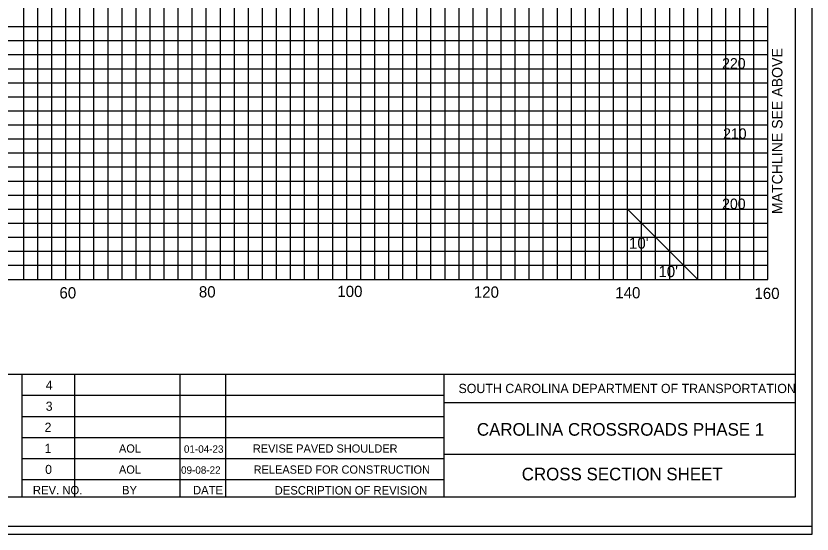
# Model space of a CAD drawing. Extents: x 967 to 1623, y 964 to 7064.
# Drawn here: x 1212.9 to 1326.3, y 4603.7 to 4677.5 of the extents above; entities that cross this region are included whole.
import ezdxf

# ---------------------------------------------------------------- set-up
doc = ezdxf.new("R2010")
doc.units = 0
for name, color, linetype in [('Default', 7, 'Continuous'), ('RD_SHT_Bndy', 7, 'Continuous'), ('RD_SHT_IplotShp', 7, 'Continuous'), ('RD_SHT_Misc1', 7, 'Continuous'), ('RD_SHT_MjGrid', 7, 'Continuous'), ('RD_SHT_MnGrid', 7, 'Continuous'), ('RD_SHT_TX', 7, 'Continuous'), ('RD_Sketch1', 7, 'Continuous'), ('RD_XS_TX_Station', 7, 'Continuous')]:
    doc.layers.add(name, color=color, linetype=linetype)

msp = doc.modelspace()

# ---------------------------------------------------------------- linework, layer by layer
at = {"layer": 'RD_SHT_Bndy'}
for p, q in [((1323.89, 4818.46), (1323.89, 4608.98)), ((996.11, 4626.49), (1323.89, 4626.49)), ((1213.76, 4608.94), (1213.76, 4626.49)), ((1221.26, 4608.95), (1221.26, 4626.48)), ((1236.26, 4608.95), (1236.26, 4626.48)), ((1242.76, 4608.95), (1242.76, 4626.48)), ((1273.88, 4608.98), (1273.88, 4626.49)), ((1213.76, 4623.48), (1273.88, 4623.48)), ((1323.93, 4622.43), (1273.88, 4622.43)), ((1213.76, 4620.48), (1273.88, 4620.48)), ((1213.76, 4617.48), (1273.88, 4617.48)), ((1213.76, 4614.48), (1273.88, 4614.48)), ((1323.89, 4615.04), (1273.88, 4615.04)), ((1213.76, 4611.48), (1273.88, 4611.48)), ((1323.89, 4608.98), (996.11, 4608.98))]:
    msp.add_line(p, q, dxfattribs=at)
at = {"layer": 'RD_SHT_IplotShp'}
for points in [[(967.41, 4603.72), (1326.28, 4603.72), (1326.28, 4823.72), (967.41, 4823.72)], [(988.52, 4604.84), (1326.28, 4604.84), (1326.28, 4822.6), (988.52, 4822.6)]]:
    msp.add_lwpolyline(points, close=True, dxfattribs=at)
at = {"layer": 'RD_SHT_MjGrid'}
for p, q in [((1220, 4640), (1220, 4810)), ((1230, 4640), (1230, 4810)), ((1240, 4640), (1240, 4810)), ((1250, 4640), (1250, 4810)), ((1260, 4640), (1260, 4810)), ((1270, 4640), (1270, 4810)), ((1280, 4640), (1280, 4810)), ((1290, 4640), (1290, 4810)), ((1300, 4640), (1300, 4810)), ((1310, 4640), (1310, 4810)), ((1320, 4640), (1320, 4810)), ((1000, 4670), (1320, 4670)), ((1000, 4660), (1320, 4660)), ((1000, 4650), (1320, 4650)), ((1000, 4640), (1320, 4640))]:
    msp.add_line(p, q, dxfattribs=at)
at = {"layer": 'RD_SHT_MnGrid'}
for p, q in [((1214, 4640), (1214, 4810)), ((1216, 4640), (1216, 4810)), ((1218, 4640), (1218, 4810)), ((1222, 4640), (1222, 4810)), ((1224, 4640), (1224, 4810)), ((1226, 4640), (1226, 4810)), ((1228, 4640), (1228, 4810)), ((1232, 4640), (1232, 4810)), ((1234, 4640), (1234, 4810)), ((1236, 4640), (1236, 4810)), ((1238, 4640), (1238, 4810)), ((1242, 4640), (1242, 4810)), ((1244, 4640), (1244, 4810)), ((1246, 4640), (1246, 4810)), ((1248, 4640), (1248, 4810)), ((1252, 4640), (1252, 4810)), ((1254, 4640), (1254, 4810)), ((1256, 4640), (1256, 4810)), ((1258, 4640), (1258, 4810)), ((1262, 4640), (1262, 4810)), ((1264, 4640), (1264, 4810)), ((1266, 4640), (1266, 4810)), ((1268, 4640), (1268, 4810)), ((1272, 4640), (1272, 4810)), ((1274, 4640), (1274, 4810)), ((1276, 4640), (1276, 4810)), ((1278, 4640), (1278, 4810)), ((1282, 4640), (1282, 4810)), ((1284, 4640), (1284, 4810)), ((1286, 4640), (1286, 4810)), ((1288, 4640), (1288, 4810)), ((1292, 4640), (1292, 4810)), ((1294, 4640), (1294, 4810)), ((1296, 4640), (1296, 4810)), ((1298, 4640), (1298, 4810)), ((1302, 4640), (1302, 4810)), ((1304, 4640), (1304, 4810)), ((1306, 4640), (1306, 4810)), ((1308, 4640), (1308, 4810)), ((1312, 4640), (1312, 4810)), ((1314, 4640), (1314, 4810)), ((1316, 4640), (1316, 4810)), ((1318, 4640), (1318, 4810)), ((1000, 4676), (1320, 4676)), ((1000, 4674), (1320, 4674)), ((1000, 4672), (1320, 4672)), ((1000, 4668), (1320, 4668)), ((1000, 4666), (1320, 4666)), ((1000, 4664), (1320, 4664)), ((1000, 4662), (1320, 4662)), ((1000, 4658), (1320, 4658)), ((1000, 4656), (1320, 4656)), ((1000, 4654), (1320, 4654)), ((1000, 4652), (1320, 4652)), ((1000, 4648), (1320, 4648)), ((1000, 4646), (1320, 4646)), ((1000, 4644), (1320, 4644)), ((1000, 4642), (1320, 4642))]:
    msp.add_line(p, q, dxfattribs=at)
at = {"layer": 'RD_SHT_TX'}
msp.add_line((1300, 4650), (1310, 4640), dxfattribs=at)
at = {"layer": 'RD_Sketch1'}
msp.add_lwpolyline([(967.41, 4603.72), (1326.28, 4603.72), (1326.28, 4823.72), (967.41, 4823.72)], close=True, dxfattribs=at)

# ---------------------------------------------------------------- texts
at = {"layer": 'Default'}
for s, p in [('220', (1313.47, 4670)), ('210', (1313.61, 4660)), ('200', (1313.47, 4650))]:
    msp.add_text(s, height=1.5, dxfattribs=at).set_placement(p)
at = {"layer": 'RD_SHT_Misc1'}
for s, height, p in [('AOL', 1.17, (1227.56, 4615.32)), ('01-04-23', 1.053, (1236.81, 4615.3)), ('REVISE PAVED SHOULDER', 1.17, (1246.63, 4615.32)), ('AOL', 1.17, (1227.56, 4612.32)), ('09-08-22', 1.053, (1236.4, 4612.31)), ('RELEASED FOR CONSTRUCTION', 1.17, (1246.74, 4612.32))]:
    msp.add_text(s, height=height, dxfattribs=at).set_placement(p)
at = {"layer": 'RD_SHT_TX'}
for s, height, p in [("10'", 1.6, (1300.21, 4644.36)), ("10'", 1.6, (1304.4, 4640.32)), ('60', 1.6, (1219.08, 4637.28)), ('80', 1.6, (1238.94, 4637.42)), ('100', 1.6, (1258.67, 4637.48)), ('120', 1.6, (1278.11, 4637.38)), ('140', 1.6, (1298.26, 4637.29)), ('160', 1.6, (1318.08, 4637.2)), ('4', 1.3, (1217.13, 4624.28)), ('SOUTH CAROLINA DEPARTMENT OF TRANSPORTATION', 1.32, (1275.92, 4623.8)), ('3', 1.3, (1217.13, 4621.28)), ('2', 1.3, (1216.97, 4618.28)), ('1', 1.3, (1216.97, 4615.28)), ('0', 1.3, (1217.05, 4612.28)), ('REV. NO.', 1.2, (1215.3, 4609.38)), ('BY', 1.2, (1227.99, 4609.38)), ('DATE', 1.2, (1238.1, 4609.38)), ('DESCRIPTION OF REVISION', 1.2, (1249.73, 4609.35))]:
    msp.add_text(s, height=height, dxfattribs=at).set_placement(p)
for s, p in [('CAROLINA CROSSROADS PHASE 1', (1278.54, 4617.73)), ('CROSS SECTION SHEET', (1284.93, 4611.37))]:
    msp.add_text(s, height=1.8, rotation=0, dxfattribs=at).set_placement(p)
at = {"layer": 'RD_XS_TX_Station'}
msp.add_text('MATCHLINE SEE ABOVE', height=1.5, rotation=90, dxfattribs=at).set_placement((1322.07, 4649.29))

doc.saveas('drawing.dxf')
